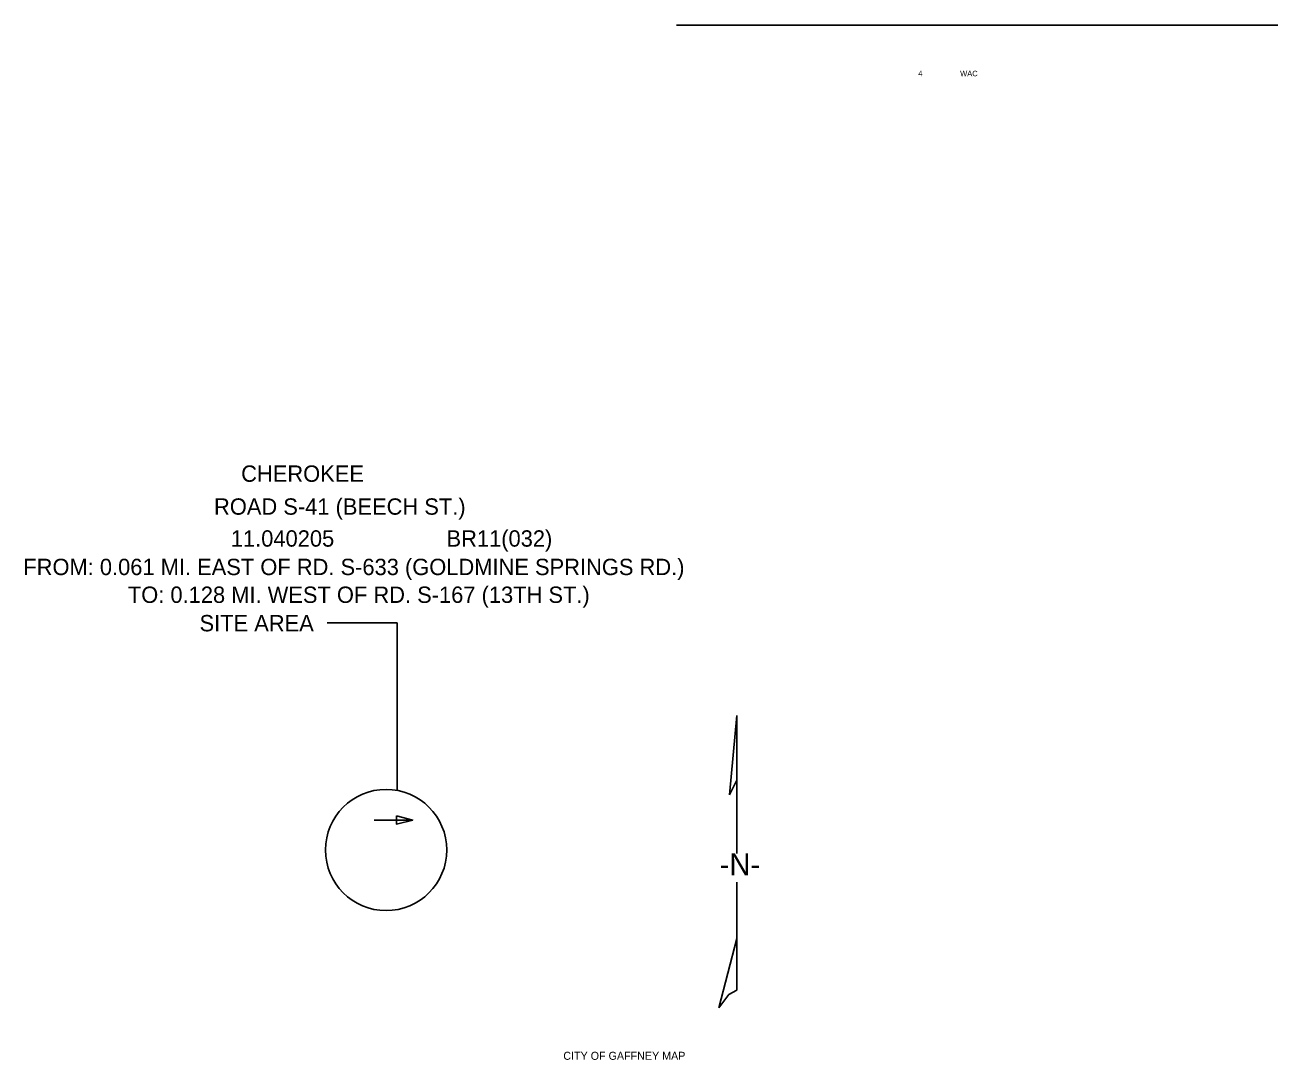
# Model space of a CAD drawing. Extents: x 160093 to 164626, y 177093 to 182727.
# Drawn here: x 161686 to 162835, y 179644 to 180593 of the extents above; entities that cross this region are included whole.
import ezdxf

# ---------------------------------------------------------------- set-up
doc = ezdxf.new("R2010")
doc.units = 0
for name, color, linetype in [('Default', 7, 'Continuous'), ('Level 40', 7, 'Continuous'), ('RD_SHT_TX', 7, 'Continuous')]:
    doc.layers.add(name, color=color, linetype=linetype)

msp = doc.modelspace()

# ---------------------------------------------------------------- linework, layer by layer
at = {"layer": 'Default'}
for p, q in [((162283.3, 180593.4), (162834.9, 180593.4)), ((161963.1, 180044.8), (162027.1, 180044.8)), ((162027.1, 179891.1), (162027.1, 180044.8)), ((162331.9, 179887.1), (162338.6, 179959.8)), ((162338.6, 179959.8), (162338.6, 179900.6)), ((162338.6, 179900.6), (162331.9, 179887.1)), ((162338.6, 179900.6), (162338.6, 179859.5)), ((162006.1, 179863.9), (162041.5, 179863.9)), ((162338.6, 179859.5), (162338.6, 179833.3)), ((162338.6, 179807.1), (162338.6, 179755.3)), ((162322.1, 179691.8), (162338.6, 179755.3)), ((162338.6, 179755.3), (162338.6, 179747.5)), ((162338.6, 179747.5), (162338.6, 179707.8))]:
    msp.add_line(p, q, dxfattribs=at)
msp.add_lwpolyline([(162026.5, 179867.7), (162041.5, 179863.9), (162026.5, 179860.2)], close=True, dxfattribs=at)
msp.add_lwpolyline([(162338.6, 179707.8), (162331.5, 179703.9), (162322.1, 179691.8)], dxfattribs=at)
msp.add_circle((162017.1, 179836.5), 55.6, dxfattribs=at)

# ---------------------------------------------------------------- texts
for s, height, p in [('CHEROKEE', 15, (161884.2, 180174.3)), ('ROAD S-41 (BEECH ST.)', 15, (161859.3, 180144.1)), ('11.040205', 15, (161874.7, 180114.8)), ('BR11(032)', 15, (162072.5, 180114.8)), ('SITE AREA', 15, (161846, 180037.1)), ('-N-', 20, (162323, 179813.4)), ('CITY OF GAFFNEY MAP', 7.351, (162179.6, 179644))]:
    msp.add_text(s, height=height, dxfattribs=at).set_placement(p)
at = {"layer": 'Level 40'}
for s, p in [('4', (162505.1, 180546.4)), ('WAC', (162543.5, 180546.4))]:
    msp.add_text(s, height=5, dxfattribs=at).set_placement(p)
at = {"layer": 'RD_SHT_TX'}
for s, p in [('FROM: 0.061 MI. EAST OF RD. S-633 (GOLDMINE SPRINGS RD.)', (161684.4, 180088.7)), ('TO: 0.128 MI. WEST OF RD. S-167 (13TH ST.)', (161780.3, 180063.2))]:
    msp.add_text(s, height=15, dxfattribs=at).set_placement(p)

doc.saveas('drawing.dxf')
